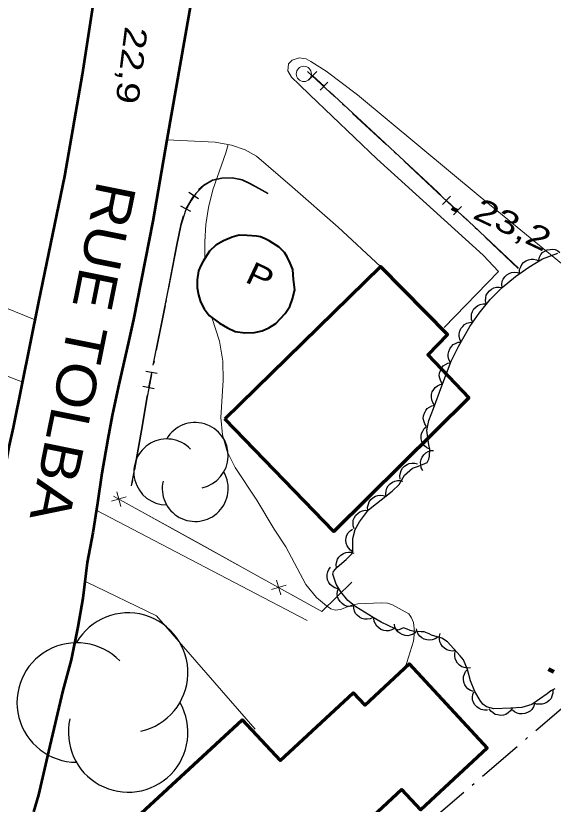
# Model space of a CAD drawing. Extents: x 356765 to 358572, y 5103174 to 5104650.
# Drawn here: x 357230.6 to 357265.9, y 5103854.4 to 5103906.2 of the extents above; entities that cross this region are included whole.
import ezdxf

# ---------------------------------------------------------------- set-up
doc = ezdxf.new("R2010")
doc.units = 0
doc.header["$LTSCALE"] = 0.6
doc.linetypes.add('DOT_DASHED', pattern=[7.7, 5, -1.2, 0.3, -1.2])
for name, color, linetype, lineweight in [('19', 7, 'Continuous', 13), ('2', 7, 'Continuous', 13), ('21', 7, 'Continuous', 53), ('3', 7, 'Continuous', 140), ('31', 7, 'Continuous', 70), ('36', 7, 'Continuous', 13), ('37', 7, 'Continuous', 13), ('38', 7, 'Continuous', 40), ('41', 7, 'DOT_DASHED', 25), ('44', 7, 'Continuous', 25)]:
    doc.layers.add(name, color=color, linetype=linetype, lineweight=lineweight)

msp = doc.modelspace()

# ---------------------------------------------------------------- linework, layer by layer
at = {"layer": '19'}
msp.add_line((357249.75, 5103866.44), (357235.88, 5103873.7), dxfattribs=at)
for points in [[(357267.08, 5103889.4), (357261.11, 5103894.28), (357253.05, 5103901), (357250.99, 5103902.54), (357249.98, 5103903.19), (357249.69, 5103903.36), (357249.23, 5103903.42), (357248.77, 5103903.28), (357248.53, 5103903.03), (357248.47, 5103902.58), (357248.72, 5103902.15), (357249.23, 5103901.67), (357249.93, 5103900.99), (357254.32, 5103896.79), (357261.31, 5103890.45), (357262.32, 5103889.38), (357258.76, 5103885.7)], [(357254.56, 5103889.71), (357251.79, 5103892.29), (357248.78, 5103894.93), (357246.42, 5103896.96), (357245.67, 5103897.38), (357244.77, 5103897.68), (357243.71, 5103897.88), (357240.54, 5103898.04)], [(357208.64, 5103879.57), (357215.22, 5103884.75), (357221.85, 5103889.75), (357224.38, 5103889.23), (357229.16, 5103887.3), (357231.89, 5103886.2)], [(357231.06, 5103882.12), (357226.45, 5103883.88), (357222.11, 5103885.38), (357218.79, 5103882.54), (357211.54, 5103876.15)], [(357246.33, 5103859.3), (357239.86, 5103866.76), (357235.23, 5103868.99)]]:
    msp.add_lwpolyline(points, dxfattribs=at)
at = {"layer": '2'}
for points in [[(357243.03, 5103890.24), (357243.02, 5103891.34), (357243.09, 5103892.48), (357243.27, 5103893.59), (357243.56, 5103894.74), (357244.41, 5103897.19), (357244.57, 5103897.72)], [(357256.18, 5103863.34), (357256.74, 5103865.08), (357256.79, 5103865.51), (357256.79, 5103865.93), (357256.73, 5103866.32), (357256.61, 5103866.63), (357256.42, 5103866.88), (357255.35, 5103867.48), (357255.03, 5103867.58), (357254.64, 5103867.62), (357253.07, 5103867.54), (357252.69, 5103867.46), (357251.93, 5103867.18), (357251.6, 5103867.12), (357251.31, 5103867.22), (357251.02, 5103867.41), (357250.36, 5103867.97), (357249.67, 5103868.82), (357248.34, 5103871.29), (357247.59, 5103872.45), (357246.45, 5103874.36), (357245.03, 5103876.51), (357244.5, 5103877.55), (357244.19, 5103878.65), (357244.08, 5103879.8), (357244.24, 5103882.22), (357244.2, 5103883.5), (357243.99, 5103884.8), (357243.49, 5103886.37)]]:
    msp.add_lwpolyline(points, dxfattribs=at)
at = {"layer": '21'}
for points in [[(357166.88, 5103926.08), (357186.19, 5103903.73), (357197.29, 5103890.67), (357216.18, 5103868.59), (357219.79, 5103864.45), (357221.65, 5103864.59), (357224.2, 5103865.18), (357226.48, 5103866.46), (357228.18, 5103868.68), (357228.77, 5103870.4), (357229.42, 5103873.87), (357230.17, 5103877.87), (357230.45, 5103879.13), (357232.13, 5103887.4), (357233.82, 5103895.66), (357235, 5103902.34), (357236.8, 5103914.18)], [(357244.37, 5103919.88), (357240.54, 5103898.04), (357239.61, 5103892.7), (357238.35, 5103886.22), (357238.04, 5103884.84), (357237.33, 5103881.75), (357236.93, 5103879.91), (357236.65, 5103878.38), (357236.27, 5103876.13), (357235.97, 5103874.17), (357235.67, 5103872.22), (357235.3, 5103870.26), (357235.02, 5103867.91), (357234.69, 5103866.04), (357234.25, 5103863.87), (357233.7, 5103861.84), (357232.75, 5103857.84), (357232.1, 5103854.99), (357231.77, 5103853.88)]]:
    msp.add_lwpolyline(points, dxfattribs=at)
at = {"layer": '3'}
for p, q in [((357259.25, 5103893.55), (357259.61, 5103893.38)), ((357265.6, 5103863.25), (357265.96, 5103863.08))]:
    msp.add_line(p, q, dxfattribs=at)
at = {"layer": '31'}
for points in [[(357244.35, 5103879.71), (357254.56, 5103889.71), (357258.97, 5103885.24), (357257.67, 5103883.91), (357260.38, 5103881.08), (357251.51, 5103872.29), (357244.35, 5103879.71)], [(357244.92, 5103844.33), (357237.41, 5103852.44), (357245.49, 5103859.92), (357247.97, 5103857.24), (357252.78, 5103861.7), (357253.53, 5103860.88), (357256.45, 5103863.59), (357261.57, 5103858.05), (357257.21, 5103854.01), (357255.98, 5103855.34), (357252.49, 5103852.11), (357252.87, 5103851.7), (357244.92, 5103844.33)]]:
    msp.add_lwpolyline(points, close=True, dxfattribs=at)
at = {"layer": '36'}
msp.add_circle((357249.5338, 5103902.3671), 0.5, dxfattribs=at)
at = {"layer": '37', "lineweight": 25}
for p, q in [((357249.87, 5103901.97), (357250.38, 5103902.52)), ((357250.86, 5103901.56), (357250.13, 5103902.25)), ((357250.6, 5103901.29), (357251.11, 5103901.83)), ((357254.88, 5103897.81), (357251.22, 5103901.22)), ((357242.61, 5103894.15), (357241.98, 5103894.57)), ((357258.64, 5103893.78), (357259.16, 5103894.33)), ((357259.63, 5103893.38), (357258.9, 5103894.06)), ((357242.11, 5103893.32), (357241.46, 5103893.68)), ((357259.37, 5103893.1), (357259.88, 5103893.65)), ((357263.64, 5103889.61), (357260, 5103893.03)), ((357239.89, 5103882.67), (357239.16, 5103882.81)), ((357239.53, 5103882.73), (357239.33, 5103881.75)), ((357239.7, 5103881.68), (357238.96, 5103881.83)), ((357238.38, 5103876.34), (357238.19, 5103875.29))]:
    msp.add_line(p, q, dxfattribs=at)
at = {"layer": '37'}
for p, q in [((357237.24, 5103874.91), (357237.51, 5103873.95)), ((357237.86, 5103874.57), (357236.89, 5103874.29)), ((357242.63, 5103871.53), (357238.25, 5103873.95)), ((357247, 5103869.11), (357242.63, 5103871.53)), ((357247.74, 5103869.1), (357248.02, 5103868.14)), ((357248.36, 5103868.76), (357247.4, 5103868.48))]:
    msp.add_line(p, q, dxfattribs=at)
at = {"layer": '37', "linetype": 'DOT_DASHED', "lineweight": 25}
for points in [[(357263.62, 5103889.59), (357258.31, 5103894.58), (357249.78, 5103902.53)], [(357247.18, 5103894.49), (357246.59, 5103894.82), (357245.99, 5103895.15), (357245.49, 5103895.38), (357244.83, 5103895.51), (357244.14, 5103895.5), (357243.53, 5103895.36), (357242.94, 5103895.01), (357242.43, 5103894.52), (357242.12, 5103894.06), (357241.75, 5103893.39), (357241.44, 5103892.4), (357241.18, 5103891.14), (357240.42, 5103887.15), (357239.21, 5103881.03), (357238.93, 5103879.3), (357238.21, 5103875.29)]]:
    msp.add_lwpolyline(points, dxfattribs=at)
at = {"layer": '37', "lineweight": 25}
for points in [[(357258.54, 5103894.4), (357258.33, 5103894.6), (357254.88, 5103897.81)], [(357247.19, 5103894.51), (357246.6, 5103894.84), (357246, 5103895.17), (357245.5, 5103895.4), (357244.83, 5103895.53), (357244.14, 5103895.52), (357243.52, 5103895.38), (357242.93, 5103895.03), (357242.62, 5103894.74)], [(357242.29, 5103894.36), (357242.1, 5103894.07), (357241.78, 5103893.5)], [(357241.61, 5103893.03), (357241.42, 5103892.41), (357241.16, 5103891.14), (357240.59, 5103888.13)], [(357240.59, 5103888.13), (357240.4, 5103887.15), (357239.62, 5103883.22)], [(357239.24, 5103881.26), (357239.19, 5103881.03), (357238.91, 5103879.3), (357238.38, 5103876.34)]]:
    msp.add_lwpolyline(points, dxfattribs=at)
at = {"layer": '37'}
for points in [[(357252.69, 5103868.97), (357250.72, 5103867.05), (357237.03, 5103874.62)], [(357252.69, 5103868.97), (357250.72, 5103867.05), (357248.75, 5103868.14)]]:
    msp.add_lwpolyline(points, dxfattribs=at)
at = {"layer": '38'}
msp.add_lwpolyline([(357245.81, 5103891.76), (357245.28, 5103891.77), (357244.82, 5103891.63), (357244.25, 5103891.41), (357243.75, 5103891.11), (357243.33, 5103890.72), (357242.92, 5103890.07), (357242.76, 5103889.77), (357242.61, 5103889.42), (357242.53, 5103888.83), (357242.52, 5103888.3), (357242.62, 5103887.86), (357242.75, 5103887.4), (357242.98, 5103886.93), (357243.32, 5103886.5), (357244, 5103885.98), (357244.52, 5103885.69), (357245.03, 5103885.45), (357245.65, 5103885.35), (357246.3, 5103885.38), (357246.8, 5103885.49), (357247.24, 5103885.68), (357247.69, 5103885.96), (357248.31, 5103886.63), (357248.62, 5103887.09), (357248.79, 5103887.58), (357248.93, 5103888.18), (357248.86, 5103888.85), (357248.8, 5103889.52), (357248.64, 5103889.94), (357248.43, 5103890.35), (357248.26, 5103890.64), (357247.91, 5103890.98), (357247.26, 5103891.39), (357247, 5103891.54), (357246.68, 5103891.66), (357246.42, 5103891.71), (357245.81, 5103891.76)], close=True, dxfattribs=at)
at = {"layer": '41'}
msp.add_line((357243.72, 5103841.19), (357324.48, 5103910.34), dxfattribs=at)
at = {"layer": '44'}
for points in [[(357264.96, 5103890.12), (357265.01, 5103890.32), (357265.11, 5103890.5), (357265.21, 5103890.63), (357265.36, 5103890.73), (357265.52, 5103890.81), (357265.71, 5103890.84), (357265.87, 5103890.86), (357266.05, 5103890.82), (357266.22, 5103890.75), (357266.36, 5103890.64)], [(357263.7, 5103889.3), (357263.71, 5103889.51), (357263.78, 5103889.7), (357263.85, 5103889.84), (357263.97, 5103889.97), (357264.12, 5103890.08), (357264.3, 5103890.15), (357264.46, 5103890.19), (357264.63, 5103890.19), (357264.82, 5103890.15), (357264.98, 5103890.08)], [(357262.55, 5103888.33), (357262.53, 5103888.54), (357262.57, 5103888.74), (357262.63, 5103888.89), (357262.73, 5103889.03), (357262.86, 5103889.16), (357263.03, 5103889.25), (357263.18, 5103889.32), (357263.36, 5103889.34), (357263.54, 5103889.32), (357263.71, 5103889.27)], [(357261.5, 5103887.25), (357261.46, 5103887.46), (357261.48, 5103887.66), (357261.51, 5103887.82), (357261.6, 5103887.97), (357261.72, 5103888.12), (357261.87, 5103888.23), (357262.01, 5103888.31), (357262.18, 5103888.35), (357262.37, 5103888.36), (357262.55, 5103888.33)], [(357260.63, 5103886.03), (357260.55, 5103886.22), (357260.54, 5103886.43), (357260.55, 5103886.59), (357260.61, 5103886.76), (357260.7, 5103886.92), (357260.83, 5103887.05), (357260.96, 5103887.16), (357261.12, 5103887.22), (357261.31, 5103887.26), (357261.49, 5103887.26)], [(357259.86, 5103884.74), (357259.77, 5103884.93), (357259.73, 5103885.13), (357259.73, 5103885.29), (357259.77, 5103885.46), (357259.85, 5103885.63), (357259.97, 5103885.78), (357260.09, 5103885.9), (357260.25, 5103885.98), (357260.42, 5103886.03), (357260.6, 5103886.05)], [(357259.17, 5103883.41), (357259.06, 5103883.6), (357259.02, 5103883.79), (357259.01, 5103883.96), (357259.05, 5103884.13), (357259.12, 5103884.3), (357259.23, 5103884.46), (357259.34, 5103884.58), (357259.49, 5103884.66), (357259.67, 5103884.73), (357259.85, 5103884.75)], [(357258.65, 5103882), (357258.53, 5103882.17), (357258.46, 5103882.37), (357258.43, 5103882.53), (357258.45, 5103882.7), (357258.5, 5103882.88), (357258.6, 5103883.05), (357258.69, 5103883.18), (357258.83, 5103883.28), (357259, 5103883.37), (357259.18, 5103883.41)], [(357258.12, 5103880.6), (357258, 5103880.77), (357257.94, 5103880.96), (357257.91, 5103881.12), (357257.92, 5103881.3), (357257.97, 5103881.48), (357258.07, 5103881.64), (357258.17, 5103881.77), (357258.31, 5103881.88), (357258.48, 5103881.96), (357258.65, 5103882)], [(357257.59, 5103879.2), (357257.47, 5103879.37), (357257.41, 5103879.56), (357257.38, 5103879.72), (357257.39, 5103879.9), (357257.45, 5103880.08), (357257.54, 5103880.24), (357257.64, 5103880.37), (357257.78, 5103880.47), (357257.95, 5103880.56), (357258.12, 5103880.6)], [(357257.8, 5103877.7), (357257.61, 5103877.79), (357257.46, 5103877.92), (357257.35, 5103878.05), (357257.28, 5103878.21), (357257.24, 5103878.39), (357257.24, 5103878.58), (357257.26, 5103878.74), (357257.34, 5103878.9), (357257.44, 5103879.06), (357257.57, 5103879.18)], [(357257.35, 5103876.3), (357257.25, 5103876.49), (357257.21, 5103876.68), (357257.2, 5103876.85), (357257.24, 5103877.02), (357257.31, 5103877.19), (357257.42, 5103877.34), (357257.54, 5103877.46), (357257.69, 5103877.55), (357257.87, 5103877.61), (357258.04, 5103877.63)], [(357255.87, 5103875.74), (357255.84, 5103875.95), (357255.88, 5103876.15), (357255.92, 5103876.31), (357256.02, 5103876.45), (357256.15, 5103876.59), (357256.31, 5103876.69), (357256.46, 5103876.76), (357256.63, 5103876.79), (357256.82, 5103876.78), (357256.99, 5103876.74)], [(357254.95, 5103874.57), (357254.92, 5103874.78), (357254.94, 5103874.98), (357254.99, 5103875.14), (357255.08, 5103875.29), (357255.2, 5103875.43), (357255.36, 5103875.53), (357255.5, 5103875.61), (357255.68, 5103875.64), (357255.86, 5103875.64), (357256.04, 5103875.61)], [(357253.73, 5103873.69), (357253.72, 5103873.9), (357253.77, 5103874.1), (357253.83, 5103874.25), (357253.93, 5103874.39), (357254.07, 5103874.52), (357254.24, 5103874.61), (357254.39, 5103874.67), (357254.56, 5103874.68), (357254.75, 5103874.67), (357254.92, 5103874.61)], [(357252.84, 5103872.48), (357252.77, 5103872.68), (357252.77, 5103872.88), (357252.78, 5103873.05), (357252.85, 5103873.21), (357252.95, 5103873.37), (357253.09, 5103873.5), (357253.22, 5103873.59), (357253.39, 5103873.65), (357253.57, 5103873.69), (357253.75, 5103873.68)], [(357252.77, 5103870.96), (357252.59, 5103871.07), (357252.46, 5103871.23), (357252.37, 5103871.36), (357252.32, 5103871.53), (357252.3, 5103871.72), (357252.32, 5103871.91), (357252.36, 5103872.06), (357252.45, 5103872.21), (357252.57, 5103872.35), (357252.72, 5103872.46)], [(357251.68, 5103869.91), (357251.65, 5103870.12), (357251.69, 5103870.32), (357251.74, 5103870.48), (357251.84, 5103870.62), (357251.97, 5103870.75), (357252.14, 5103870.85), (357252.29, 5103870.92), (357252.46, 5103870.94), (357252.65, 5103870.93), (357252.82, 5103870.88)], [(357251.76, 5103868.53), (357251.56, 5103868.59), (357251.39, 5103868.7), (357251.26, 5103868.81), (357251.17, 5103868.95), (357251.09, 5103869.12), (357251.06, 5103869.31), (357251.06, 5103869.48), (357251.1, 5103869.65), (357251.18, 5103869.81), (357251.29, 5103869.96)], [(357252.74, 5103867.38), (357252.53, 5103867.36), (357252.33, 5103867.4), (357252.18, 5103867.46), (357252.04, 5103867.56), (357251.91, 5103867.69), (357251.81, 5103867.86), (357251.75, 5103868.01), (357251.73, 5103868.19), (357251.74, 5103868.37), (357251.8, 5103868.54)], [(357254.08, 5103866.65), (357253.89, 5103866.56), (357253.69, 5103866.54), (357253.52, 5103866.54), (357253.35, 5103866.59), (357253.19, 5103866.67), (357253.04, 5103866.79), (357252.93, 5103866.91), (357252.86, 5103867.07), (357252.81, 5103867.25), (357252.8, 5103867.43)], [(357255.49, 5103865.93), (357255.31, 5103865.83), (357255.12, 5103865.78), (357254.95, 5103865.76), (357254.78, 5103865.79), (357254.6, 5103865.85), (357254.45, 5103865.96), (357254.32, 5103866.07), (357254.23, 5103866.22), (357254.16, 5103866.39), (357254.13, 5103866.57)], [(357256.88, 5103865.67), (357256.71, 5103865.55), (357256.52, 5103865.48), (357256.36, 5103865.45), (357256.18, 5103865.47), (357256, 5103865.52), (357255.84, 5103865.62), (357255.71, 5103865.71), (357255.6, 5103865.86), (357255.52, 5103866.02), (357255.48, 5103866.2)], [(357258.33, 5103865.36), (357258.15, 5103865.24), (357257.96, 5103865.18), (357257.8, 5103865.15), (357257.62, 5103865.17), (357257.44, 5103865.22), (357257.28, 5103865.32), (357257.15, 5103865.42), (357257.05, 5103865.56), (357256.97, 5103865.73), (357256.93, 5103865.91)], [(357259.49, 5103864.47), (357259.28, 5103864.44), (357259.08, 5103864.48), (357258.92, 5103864.52), (357258.78, 5103864.62), (357258.64, 5103864.74), (357258.54, 5103864.91), (357258.47, 5103865.05), (357258.44, 5103865.23), (357258.44, 5103865.41), (357258.49, 5103865.59)], [(357260.47, 5103863.34), (357260.26, 5103863.31), (357260.06, 5103863.35), (357259.91, 5103863.4), (357259.76, 5103863.51), (357259.63, 5103863.64), (357259.53, 5103863.8), (357259.47, 5103863.95), (357259.45, 5103864.12), (357259.45, 5103864.31), (357259.5, 5103864.48)], [(357260.67, 5103861.78), (357260.48, 5103861.84), (357260.31, 5103861.96), (357260.19, 5103862.08), (357260.1, 5103862.23), (357260.04, 5103862.4), (357260.02, 5103862.59), (357260.02, 5103862.76), (357260.08, 5103862.92), (357260.16, 5103863.09), (357260.28, 5103863.22)], [(357265.89, 5103861.88), (357265.89, 5103861.68), (357265.83, 5103861.48), (357265.77, 5103861.33), (357265.65, 5103861.2), (357265.51, 5103861.08), (357265.34, 5103861), (357265.18, 5103860.94), (357265.01, 5103860.94), (357264.82, 5103860.96), (357264.65, 5103861.03)], [(357261.6, 5103860.56), (357261.39, 5103860.55), (357261.19, 5103860.6), (357261.04, 5103860.66), (357260.9, 5103860.77), (357260.77, 5103860.9), (357260.68, 5103861.07), (357260.62, 5103861.23), (357260.61, 5103861.4), (357260.63, 5103861.59), (357260.69, 5103861.76)], [(357264.68, 5103860.98), (357264.61, 5103860.78), (357264.5, 5103860.61), (357264.39, 5103860.49), (357264.23, 5103860.4), (357264.06, 5103860.33), (357263.87, 5103860.31), (357263.71, 5103860.31), (357263.54, 5103860.36), (357263.37, 5103860.45), (357263.24, 5103860.56)], [(357263.21, 5103860.68), (357263.1, 5103860.51), (357262.95, 5103860.37), (357262.81, 5103860.28), (357262.64, 5103860.23), (357262.46, 5103860.21), (357262.27, 5103860.24), (357262.11, 5103860.28), (357261.96, 5103860.37), (357261.82, 5103860.5), (357261.71, 5103860.64)]]:
    msp.add_lwpolyline(points, dxfattribs=at)
at = {"layer": '44', "linetype": 'DOT_DASHED'}
for points in [[(357254.08, 5103866.65), (357252.95, 5103867.34), (357252.43, 5103867.76), (357251.96, 5103868.34), (357251.66, 5103868.84), (357251.44, 5103869.5), (357251.49, 5103869.66), (357251.58, 5103869.8), (357251.72, 5103869.95), (357252.31, 5103870.45), (357252.68, 5103870.84), (357252.74, 5103871.01), (357252.76, 5103871.25), (357252.74, 5103871.84), (357252.9, 5103872.42), (357253.19, 5103872.94), (357253.79, 5103873.73), (357254.3, 5103874.13), (357255.34, 5103874.94), (357255.8, 5103875.38), (357256.15, 5103875.99), (357256.68, 5103876.46), (357257.06, 5103876.58), (357257.63, 5103876.84), (357257.74, 5103877.05), (357257.79, 5103877.25), (357257.81, 5103877.7), (357257.75, 5103878), (357257.61, 5103878.94), (357257.74, 5103879.59), (357258.04, 5103880.38), (357258.6, 5103881.87), (357259.21, 5103883.5), (357259.7, 5103884.46), (357260.44, 5103885.76), (357261.06, 5103886.65), (357261.78, 5103887.54), (357262.56, 5103888.34), (357263.44, 5103889.05), (357264.31, 5103889.67), (357265.2, 5103890.21), (357266.22, 5103890.59)], [(357266.01, 5103861.95), (357265.75, 5103861.82), (357265.52, 5103861.63), (357264.51, 5103860.93), (357263.85, 5103860.74), (357263.13, 5103860.68), (357262.01, 5103860.65), (357261.53, 5103860.78), (357261.3, 5103860.95), (357261.11, 5103861.2), (357260.77, 5103861.79), (357260.48, 5103862.49), (357260.28, 5103863.23), (357260.02, 5103863.87), (357259.8, 5103864.13), (357258.97, 5103865.05), (357258.59, 5103865.28), (357257.92, 5103865.49), (357257.76, 5103865.58), (357257.43, 5103865.71), (357257.25, 5103865.7), (357256.7, 5103865.75), (357256.51, 5103865.79), (357256.32, 5103865.88), (357256.08, 5103865.97), (357255.72, 5103865.82), (357255.54, 5103865.91), (357254.62, 5103866.34), (357254.08, 5103866.65)]]:
    msp.add_lwpolyline(points, dxfattribs=at)
at = {"layer": '44'}
for centre, radius, start, end in [((357242.3957, 5103877.2935), 2.1685, 282.26917, 149.72626), ((357240.5308, 5103876.2092), 2.1685, 44.11537, 269.80396), ((357242.3957, 5103875.125), 2.1685, 166.93686, 29.62122), ((357237.9906, 5103863.0232), 3.9281, 282.26917, 149.72626), ((357234.6125, 5103861.0592), 3.9281, 44.11537, 269.80396), ((357237.9906, 5103859.0952), 3.9281, 166.93686, 29.62122)]:
    msp.add_arc(centre, radius, start, end, dxfattribs=at)

# ---------------------------------------------------------------- texts
at = {"layer": '21', "width": 1.15}
msp.add_text('RUE TOLBA', height=2.6, rotation=258.634, dxfattribs=at).set_placement((357235.98, 5103895.43))
at = {"layer": '3'}
for s, rotation, width, p in [('22,9   ', 262.846, 1.3, (357237.79, 5103905.54)), ('23,2   ', 334.619, 1.35, (357260.55, 5103892.92))]:
    msp.add_text(s, height=1.5, rotation=rotation, dxfattribs=dict(at, width=width)).set_placement(p)
at = {"layer": '38', "width": 1.25}
msp.add_text('P', height=1.5, rotation=334.72, dxfattribs=at).set_placement((357245.59, 5103888.73))

doc.saveas('drawing.dxf')
